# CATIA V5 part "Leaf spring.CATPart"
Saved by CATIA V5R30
Part number: Part1
Material "Steel": density 7860 kg/m3, Young's modulus 2e+11 Pa, Poisson ratio 0.266, thermal expansion 1.17e-05 1/K
Bounding box of the stored display mesh (mm): x 0 to 6, y -52.464 to 52.464, z -1 to 10.425
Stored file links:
  D:\PROJECTS\CATIA V56R 2020\Resources\Tutorial Files\c19_catia_v5_6r2019_tut\C19_tut_03.CATPart\Leaf spring.CATPart
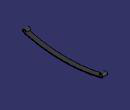
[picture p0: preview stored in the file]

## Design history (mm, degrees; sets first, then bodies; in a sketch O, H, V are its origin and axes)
Body1 (main body), material "Steel"
  Sketch1 on yz-plane, origin (0, 0, 0), H (0, 1, 0), V (0, 0, 1)
    arc A1 centre (0, 199) radius 199 from (-50.3797, 6.4828) to (50.3797, 6.4828) ccw
    point P1 (0, 199)
    arc A2 centre (0, 199) radius 200 from (-50.6329, 5.5154) to (50.6329, 5.5154) ccw
    arc A3 centre (-50, 7.9339) radius 2.5 from (-47.5, 7.9339) to (-50.6329, 5.5154) ccw
    point P2 (-50, 7.9339)
    arc A4 centre (50, 7.9339) radius 2.5 from (47.5, 7.9339) to (50.6329, 5.5154) cw
    arc A5 centre (-50, 7.9339) radius 1.5 from (-48.5, 7.9339) to (-50.3797, 6.4828) ccw
    point P4 (50, 7.9339)
    arc A6 centre (50, 7.9339) radius 1.5 from (48.5, 7.9339) to (50.3797, 6.4828) cw
    point P8 (50.3797, 6.4828)
    line L1 (48.5, 7.9339) -> (47.5, 7.9339)
    point P10 (-47.5, 7.9339)
    point P11 (50.3797, 6.4828)
    line L2 (-47.5, 7.9339) -> (-48.5, 7.9339)
    distance A1 A2 = 1
    distance P4 P2 = 100
    radius A3 = 2.5
    radius A2 = 200
    coincidence: A1 O, P1 V, A6 P8, L1 P10, A1 P11, L1 L2, L2 P2
    concentricity: A1 A2
    tangency: A3 A2, A5 A1
    symmetry: A3 A4 V, A5 A6 V
    horizontal: L1 H, L2 H
  Pad1: profile Sketch1, direction (1, 0, 0), length 6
